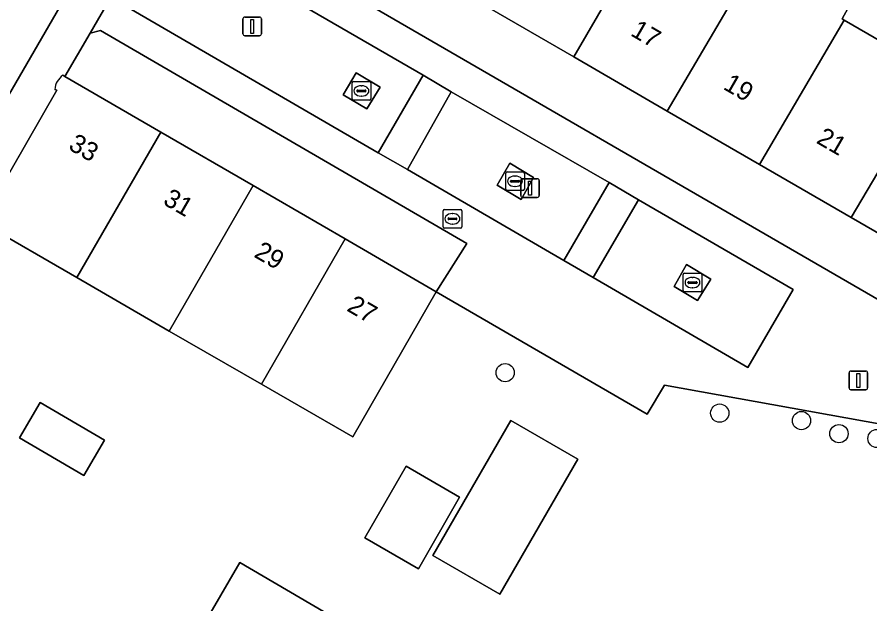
# Model space of a CAD drawing. Extents: x 160023 to 161302, y 384750 to 385707.
# Drawn here: x 160323.26 to 160368.97, y 385017.71 to 385049.15 of the extents above; entities that cross this region are included whole.
import ezdxf

# ---------------------------------------------------------------- set-up
doc = ezdxf.new("R2010")
doc.units = 0
for name, color, linetype in [('IMGEO_Boom', 7, 'Continuous'), ('IMGEO_Brandkraan', 7, 'Continuous'), ('IMGEO_Erf', 7, 'Continuous'), ('IMGEO_Groenvoorziening', 7, 'Continuous'), ('IMGEO_Kolk', 7, 'Continuous'), ('IMGEO_Lichtmast', 7, 'Continuous'), ('IMGEO_Muur', 7, 'Continuous'), ('IMGEO_Pand', 7, 'Continuous'), ('IMGEO_Pand_nummerreeks', 7, 'Continuous'), ('IMGEO_Rijbaan_lokaal_open', 7, 'Continuous'), ('IMGEO_Voetpad_open', 7, 'Continuous')]:
    doc.layers.add(name, color=color, linetype=linetype)

msp = doc.modelspace()

# ---------------------------------------------------------------- linework, layer by layer
at = {"layer": 'IMGEO_Boom'}
for centre in [(160349.417, 385030.095), (160360.917, 385027.93), (160365.298, 385027.531), (160367.305, 385026.828), (160369.342, 385026.569)]:
    msp.add_circle(centre, 0.489, dxfattribs=at)
at = {"layer": 'IMGEO_Brandkraan'}
for p, q in [((160346.091, 385037.915), (160346.091, 385038.767)), ((160346.166, 385038.841), (160347.018, 385038.841)), ((160347.092, 385038.767), (160347.092, 385037.915)), ((160346.35, 385038.335), (160346.35, 385038.347)), ((160346.788, 385038.298), (160346.39, 385038.298)), ((160346.393, 385038.384), (160346.791, 385038.384)), ((160346.579, 385038.621), (160346.604, 385038.621)), ((160346.834, 385038.347), (160346.834, 385038.335)), ((160347.018, 385037.841), (160346.166, 385037.841)), ((160346.602, 385038.061), (160346.577, 385038.061))]:
    msp.add_line(p, q, dxfattribs=at)
for points in [[(160346.091, 385037.915), (160346.091, 385038.767)], [(160346.166, 385038.841), (160347.018, 385038.841)], [(160347.092, 385038.767), (160347.092, 385037.915)], [(160347.018, 385037.841), (160346.166, 385037.841)]]:
    msp.add_lwpolyline(points, dxfattribs=at)
for centre, radius, start, end in [((160346.168, 385038.765), 0.0765, 91.552, 178.448), ((160346.168, 385038.765), 0.0765, 91.552, 178.448), ((160347.016, 385038.765), 0.0765, 1.552, 88.448), ((160347.016, 385038.765), 0.0765, 1.552, 88.448), ((160346.39, 385038.344), 0.0403, 85.8775, 175.7526), ((160346.387, 385038.334), 0.0366, 178.938, 274.7102), ((160346.791, 385038.341), 0.043, 264.8664, 352.4533), ((160346.795, 385038.346), 0.0386, 1.7309, 96.639), ((160346.168, 385037.917), 0.0765, 181.552, 268.448), ((160346.168, 385037.917), 0.0765, 181.552, 268.448), ((160347.016, 385037.917), 0.0765, 271.552, 358.448), ((160347.016, 385037.917), 0.0765, 271.552, 358.448)]:
    msp.add_arc(centre, radius, start, end, dxfattribs=at)
for centre, major_axis, ratio, start_param, end_param in [((160346.578, 385038.341), (-0.387, 0.002), 0.722429, 4.712389, 7.853982), ((160346.603, 385038.341), (-0.39, 0.002), 0.717154, 1.570796, 4.712389)]:
    msp.add_ellipse(centre, major_axis=major_axis, ratio=ratio, start_param=start_param, end_param=end_param, dxfattribs=at)
at = {"layer": 'IMGEO_Erf'}
for points in [[(160341.602, 385073.205), (160337.624, 385066.346), (160342.79, 385063.353), (160347.722, 385060.496), (160348.234, 385060.199), (160349.711, 385062.77), (160354.025, 385060.275), (160352.506, 385057.725), (160352.646, 385057.644), (160357.595, 385054.777), (160362.648, 385051.85), (160364.148, 385054.413), (160368.892, 385051.644), (160367.47, 385049.057), (160367.581, 385048.992), (160372.53, 385046.125)], [(160372.902, 385035.551), (160367.963, 385038.408), (160363.04, 385041.256), (160358.102, 385044.113), (160353.093, 385047.011), (160348.11, 385049.893), (160343.179, 385052.746), (160338.224, 385055.613), (160333.103, 385058.575), (160331.774, 385056.226), (160331.905, 385055.737), (160376.591, 385029.85)], [(160374.524, 385026.448), (160357.964, 385029.422), (160357.035, 385027.882), (160345.726, 385034.421), (160341.247, 385026.657), (160336.353, 385029.481), (160331.416, 385032.329), (160326.462, 385035.188), (160321.307, 385038.162)]]:
    msp.add_lwpolyline(points, dxfattribs=at)
for points in [[(160325.824, 385045.965), (160330.97, 385042.98), (160335.906, 385040.117), (160340.833, 385037.259), (160345.726, 385034.421), (160347.367, 385037.02), (160327.729, 385048.436), (160327.17, 385048.287)], [(160323.382, 385026.602), (160324.496, 385028.507), (160327.95, 385026.489), (160326.844, 385024.588)], [(160345.536, 385020.303), (160349.718, 385027.541), (160353.315, 385025.463), (160349.132, 385018.225)], [(160341.894, 385021.255), (160344.107, 385025.086), (160346.977, 385023.428), (160344.764, 385019.596)], [(160337.636, 385011.392), (160336.114, 385008.781), (160334.557, 385006.112), (160330.723, 385008.347), (160330.705, 385008.315), (160329.641, 385006.491), (160326.163, 385008.519), (160327.15, 385010.377), (160329.004, 385009.296), (160330.562, 385011.967), (160332.084, 385014.578), (160333.606, 385017.189), (160335.201, 385019.925), (160339.688, 385017.309), (160340.731, 385016.7), (160339.158, 385014.003)]]:
    msp.add_lwpolyline(points, close=True, dxfattribs=at)
at = {"layer": 'IMGEO_Groenvoorziening'}
for points in [[(160330.679, 385054.349), (160328.289, 385050.224), (160342.619, 385041.873), (160345.03, 385046.042)], [(160340.743, 385044.978), (160341.431, 385046.155), (160342.717, 385045.402), (160342.011, 385044.233)], [(160346.519, 385045.149), (160344.191, 385040.975), (160352.567, 385036.101), (160354.982, 385040.282)], [(160348.983, 385040.143), (160349.672, 385041.315), (160350.93, 385040.559), (160350.268, 385039.383)], [(160356.558, 385039.366), (160354.142, 385035.197), (160362.418, 385030.367), (160364.86, 385034.548)], [(160358.478, 385034.708), (160359.127, 385035.9), (160360.445, 385035.114), (160359.723, 385033.963)]]:
    msp.add_lwpolyline(points, close=True, dxfattribs=at)
at = {"layer": 'IMGEO_Kolk'}
for p, q in [((160341.214, 385044.766), (160341.214, 385045.618)), ((160341.289, 385045.692), (160342.141, 385045.692)), ((160342.215, 385045.618), (160342.215, 385044.766)), ((160341.473, 385045.186), (160341.473, 385045.198)), ((160341.911, 385045.149), (160341.513, 385045.149)), ((160341.516, 385045.235), (160341.914, 385045.235)), ((160341.702, 385045.472), (160341.727, 385045.472)), ((160341.957, 385045.198), (160341.957, 385045.186)), ((160342.141, 385044.692), (160341.289, 385044.692)), ((160341.725, 385044.912), (160341.7, 385044.912)), ((160349.444, 385039.928), (160349.444, 385040.78)), ((160349.519, 385040.854), (160350.371, 385040.854)), ((160349.932, 385040.634), (160349.957, 385040.634)), ((160350.445, 385040.78), (160350.445, 385039.928)), ((160349.703, 385040.348), (160349.703, 385040.36)), ((160350.141, 385040.311), (160349.743, 385040.311)), ((160349.746, 385040.397), (160350.144, 385040.397)), ((160350.187, 385040.36), (160350.187, 385040.348)), ((160350.371, 385039.854), (160349.519, 385039.854)), ((160349.955, 385040.074), (160349.93, 385040.074)), ((160358.956, 385034.499), (160358.956, 385035.351)), ((160359.031, 385035.425), (160359.883, 385035.425)), ((160359.444, 385035.205), (160359.469, 385035.205)), ((160359.957, 385035.351), (160359.957, 385034.499)), ((160359.215, 385034.919), (160359.215, 385034.931)), ((160359.653, 385034.882), (160359.255, 385034.882)), ((160359.258, 385034.968), (160359.656, 385034.968)), ((160359.467, 385034.645), (160359.442, 385034.645)), ((160359.699, 385034.931), (160359.699, 385034.919)), ((160359.883, 385034.425), (160359.031, 385034.425))]:
    msp.add_line(p, q, dxfattribs=at)
for points in [[(160341.214, 385044.766), (160341.214, 385045.618)], [(160341.289, 385045.692), (160342.141, 385045.692)], [(160342.215, 385045.618), (160342.215, 385044.766)], [(160342.141, 385044.692), (160341.289, 385044.692)], [(160349.444, 385039.928), (160349.444, 385040.78)], [(160349.519, 385040.854), (160350.371, 385040.854)], [(160350.445, 385040.78), (160350.445, 385039.928)], [(160350.371, 385039.854), (160349.519, 385039.854)], [(160358.956, 385034.499), (160358.956, 385035.351)], [(160359.031, 385035.425), (160359.883, 385035.425)], [(160359.957, 385035.351), (160359.957, 385034.499)], [(160359.883, 385034.425), (160359.031, 385034.425)]]:
    msp.add_lwpolyline(points, dxfattribs=at)
for centre, radius, start, end in [((160341.291, 385045.616), 0.0765, 91.552, 178.448), ((160341.291, 385045.616), 0.0765, 91.552, 178.448), ((160342.139, 385045.616), 0.0765, 1.552, 88.448), ((160342.139, 385045.616), 0.0765, 1.552, 88.448), ((160341.513, 385045.195), 0.0403, 85.8775, 175.7526), ((160341.51, 385045.185), 0.0366, 178.938, 274.7102), ((160341.914, 385045.192), 0.043, 264.8664, 352.4533), ((160341.918, 385045.197), 0.0386, 1.7309, 96.639), ((160341.291, 385044.768), 0.0765, 181.552, 268.448), ((160341.291, 385044.768), 0.0765, 181.552, 268.448), ((160342.139, 385044.768), 0.0765, 271.552, 358.448), ((160342.139, 385044.768), 0.0765, 271.552, 358.448), ((160349.521, 385040.778), 0.0765, 91.552, 178.448), ((160349.521, 385040.778), 0.0765, 91.552, 178.448), ((160350.369, 385040.778), 0.0765, 1.552, 88.448), ((160350.369, 385040.778), 0.0765, 1.552, 88.448), ((160349.743, 385040.357), 0.0403, 85.8775, 175.7526), ((160349.74, 385040.347), 0.0366, 178.938, 274.7102), ((160350.144, 385040.354), 0.043, 264.8664, 352.4533), ((160350.148, 385040.359), 0.0386, 1.7309, 96.639), ((160349.521, 385039.93), 0.0765, 181.552, 268.448), ((160349.521, 385039.93), 0.0765, 181.552, 268.448), ((160350.369, 385039.93), 0.0765, 271.552, 358.448), ((160350.369, 385039.93), 0.0765, 271.552, 358.448), ((160359.033, 385035.349), 0.0765, 91.552, 178.448), ((160359.033, 385035.349), 0.0765, 91.552, 178.448), ((160359.881, 385035.349), 0.0765, 1.552, 88.448), ((160359.881, 385035.349), 0.0765, 1.552, 88.448), ((160359.255, 385034.928), 0.0403, 85.8775, 175.7526), ((160359.252, 385034.918), 0.0366, 178.938, 274.7102), ((160359.656, 385034.925), 0.043, 264.8664, 352.4533), ((160359.66, 385034.93), 0.0386, 1.7309, 96.639), ((160359.033, 385034.501), 0.0765, 181.552, 268.448), ((160359.033, 385034.501), 0.0765, 181.552, 268.448), ((160359.881, 385034.501), 0.0765, 271.552, 358.448), ((160359.881, 385034.501), 0.0765, 271.552, 358.448)]:
    msp.add_arc(centre, radius, start, end, dxfattribs=at)
for centre, major_axis, ratio, start_param, end_param in [((160341.701, 385045.192), (-0.387, 0.002), 0.722429, 4.712389, 7.853982), ((160341.726, 385045.192), (-0.39, 0.002), 0.717154, 1.570796, 4.712389), ((160349.931, 385040.354), (-0.387, 0.002), 0.722429, 4.712389, 7.853982), ((160349.956, 385040.354), (-0.39, 0.002), 0.717154, 1.570796, 4.712389), ((160359.443, 385034.925), (-0.387, 0.002), 0.722429, 4.712389, 7.853982), ((160359.468, 385034.925), (-0.39, 0.002), 0.717154, 1.570796, 4.712389)]:
    msp.add_ellipse(centre, major_axis=major_axis, ratio=ratio, start_param=start_param, end_param=end_param, dxfattribs=at)
at = {"layer": 'IMGEO_Lichtmast'}
for p, q in [((160335.365, 385048.25), (160335.365, 385049.05)), ((160335.365, 385049.05), (160335.365, 385048.25)), ((160335.465, 385049.15), (160336.255, 385049.15)), ((160336.255, 385049.15), (160335.465, 385049.15)), ((160336.355, 385049.05), (160336.355, 385048.25)), ((160336.355, 385048.25), (160336.355, 385049.05)), ((160336.255, 385048.15), (160335.465, 385048.15)), ((160335.465, 385048.15), (160336.255, 385048.15)), ((160350.25, 385039.585), (160350.25, 385040.385)), ((160350.25, 385040.385), (160350.25, 385039.585)), ((160350.35, 385040.485), (160351.14, 385040.485)), ((160351.14, 385040.485), (160350.35, 385040.485)), ((160351.24, 385040.385), (160351.24, 385039.585)), ((160351.24, 385039.585), (160351.24, 385040.385)), ((160351.14, 385039.485), (160350.35, 385039.485)), ((160350.35, 385039.485), (160351.14, 385039.485)), ((160367.849, 385029.282), (160367.849, 385030.082)), ((160367.849, 385030.082), (160367.849, 385029.282)), ((160367.949, 385030.182), (160368.739, 385030.182)), ((160368.739, 385030.182), (160367.949, 385030.182)), ((160368.839, 385030.082), (160368.839, 385029.282)), ((160368.839, 385029.282), (160368.839, 385030.082)), ((160368.739, 385029.182), (160367.949, 385029.182)), ((160367.949, 385029.182), (160368.739, 385029.182))]:
    msp.add_line(p, q, dxfattribs=at)
for points in [[(160335.785, 385049.025), (160335.935, 385049.025), (160335.935, 385048.275), (160335.785, 385048.275), (160335.785, 385049.025)], [(160350.67, 385040.36), (160350.82, 385040.36), (160350.82, 385039.61), (160350.67, 385039.61), (160350.67, 385040.36)], [(160368.269, 385030.057), (160368.419, 385030.057), (160368.419, 385029.307), (160368.269, 385029.307), (160368.269, 385030.057)]]:
    msp.add_lwpolyline(points, dxfattribs=at)
for centre, start, end in [((160335.465, 385049.05), 90, 180), ((160335.465, 385049.05), 90, 180), ((160336.255, 385049.05), 0, 90), ((160336.255, 385049.05), 360, 90), ((160335.465, 385048.25), 180, 270), ((160335.465, 385048.25), 180, 270), ((160336.255, 385048.25), 270, 0), ((160336.255, 385048.25), 270, 0), ((160350.35, 385040.385), 90, 180), ((160350.35, 385040.385), 90, 180), ((160351.14, 385040.385), 0, 90), ((160351.14, 385040.385), 360, 90), ((160350.35, 385039.585), 180, 270), ((160350.35, 385039.585), 180, 270), ((160351.14, 385039.585), 270, 0), ((160351.14, 385039.585), 270, 0), ((160367.949, 385030.082), 90, 180), ((160367.949, 385030.082), 90, 180), ((160368.739, 385030.082), 0, 90), ((160368.739, 385030.082), 360, 90), ((160367.949, 385029.282), 180, 270), ((160367.949, 385029.282), 180, 270), ((160368.739, 385029.282), 270, 0), ((160368.739, 385029.282), 270, 0)]:
    msp.add_arc(centre, 0.1, start, end, dxfattribs=at)
at = {"layer": 'IMGEO_Muur'}
msp.add_lwpolyline([(160345.726, 385034.421), (160357.035, 385027.882)], dxfattribs=at)
at = {"layer": 'IMGEO_Pand'}
for points in [[(160352.646, 385057.644), (160348.11, 385049.893), (160353.093, 385047.011), (160357.595, 385054.777)], [(160357.595, 385054.777), (160353.093, 385047.011), (160358.102, 385044.113), (160362.648, 385051.85)], [(160367.581, 385048.992), (160367.47, 385049.057), (160368.892, 385051.644), (160364.148, 385054.413), (160362.648, 385051.85), (160358.102, 385044.113), (160363.04, 385041.256)], [(160367.581, 385048.992), (160363.04, 385041.256), (160367.963, 385038.408), (160372.53, 385046.125)], [(160372.53, 385046.125), (160367.963, 385038.408), (160372.902, 385035.551), (160377.462, 385043.268)], [(160326.462, 385035.188), (160331.416, 385032.329), (160335.906, 385040.117), (160330.97, 385042.98)], [(160331.416, 385032.329), (160336.353, 385029.481), (160340.833, 385037.259), (160335.906, 385040.117)], [(160336.353, 385029.481), (160341.247, 385026.657), (160345.726, 385034.421), (160340.833, 385037.259)], [(160326.844, 385024.588), (160327.95, 385026.489), (160324.496, 385028.507), (160323.382, 385026.602)], [(160353.315, 385025.463), (160349.718, 385027.541), (160345.536, 385020.303), (160349.132, 385018.225)], [(160341.894, 385021.255), (160344.764, 385019.596), (160346.977, 385023.428), (160344.107, 385025.086)], [(160339.158, 385014.003), (160340.731, 385016.7), (160339.688, 385017.309), (160335.201, 385019.925), (160333.606, 385017.189)]]:
    msp.add_lwpolyline(points, close=True, dxfattribs=at)
msp.add_lwpolyline([(160325.286, 385045.271), (160325.384, 385045.224), (160321.307, 385038.162), (160326.462, 385035.188), (160330.97, 385042.98), (160325.824, 385045.965), (160325.713, 385046.029)], dxfattribs=at)
msp.add_arc((160326.248, 385045.228), 0.963, 123.7441, 177.4686, dxfattribs=at)
at = {"layer": 'IMGEO_Rijbaan_lokaal_open'}
msp.add_lwpolyline([(160298.133, 385002.441), (160299.328, 385004.495), (160301.364, 385007.975), (160310.622, 385023.967), (160312.148, 385026.623), (160312.692, 385027.574), (160315.342, 385032.116), (160319.833, 385039.862), (160338.122, 385071.424)], dxfattribs=at)
at = {"layer": 'IMGEO_Voetpad_open'}
for points in [[(160343.285, 385080.295), (160342.782, 385079.444), (160340.106, 385074.885), (160338.122, 385071.424), (160319.833, 385039.862), (160315.342, 385032.116), (160312.692, 385027.574), (160312.148, 385026.623)], [(160325.713, 385046.029), (160325.824, 385045.965), (160327.17, 385048.287), (160328.289, 385050.224), (160330.679, 385054.349)], [(160300.306, 384997.12), (160301.947, 385000), (160302.566, 385001.087), (160302.587, 385001.917), (160306.193, 385008.153), (160309.494, 385013.861), (160312.785, 385019.552), (160316.226, 385025.503), (160318.446, 385029.357), (160319.024, 385030.345), (160317.354, 385031.285), (160321.307, 385038.162), (160325.384, 385045.224), (160325.286, 385045.271)]]:
    msp.add_lwpolyline(points, dxfattribs=at)
for points in [[(160331.905, 385055.737), (160331.774, 385056.226), (160330.679, 385054.349), (160345.03, 385046.042), (160346.519, 385045.149), (160354.982, 385040.282), (160356.558, 385039.366), (160364.86, 385034.548), (160362.418, 385030.367), (160354.142, 385035.197), (160352.567, 385036.101), (160344.191, 385040.975), (160342.619, 385041.873), (160328.289, 385050.224), (160327.17, 385048.287), (160327.729, 385048.436), (160347.367, 385037.02), (160345.726, 385034.421), (160357.035, 385027.882), (160357.964, 385029.422), (160374.524, 385026.448), (160376.591, 385029.85)], [(160342.011, 385044.233), (160342.717, 385045.402), (160341.431, 385046.155), (160340.743, 385044.978)], [(160346.519, 385045.149), (160345.03, 385046.042), (160342.619, 385041.873), (160344.191, 385040.975)], [(160350.268, 385039.383), (160350.93, 385040.559), (160349.672, 385041.315), (160348.983, 385040.143)], [(160356.558, 385039.366), (160354.982, 385040.282), (160352.567, 385036.101), (160354.142, 385035.197)], [(160359.723, 385033.963), (160360.445, 385035.114), (160359.127, 385035.9), (160358.478, 385034.708)]]:
    msp.add_lwpolyline(points, close=True, dxfattribs=at)
msp.add_arc((160326.248, 385045.228), 0.963, 123.7441, 177.4686, dxfattribs=at)

# ---------------------------------------------------------------- texts
at = {"layer": 'IMGEO_Pand_nummerreeks'}
for s, rotation, p in [('17', 329.95, (160356.084, 385048.191)), ('19', 329.9484, (160361.051, 385045.318)), ('33', 329.8845, (160325.952, 385042.099)), ('21', 329.95, (160366.039, 385042.432)), ('31', 329.8845, (160331.024, 385039.157)), ('29', 329.8845, (160335.903, 385036.327)), ('27', 329.8845, (160340.878, 385033.441))]:
    msp.add_text(s, height=1, rotation=rotation, dxfattribs=at).set_placement(p)

doc.saveas('drawing.dxf')
